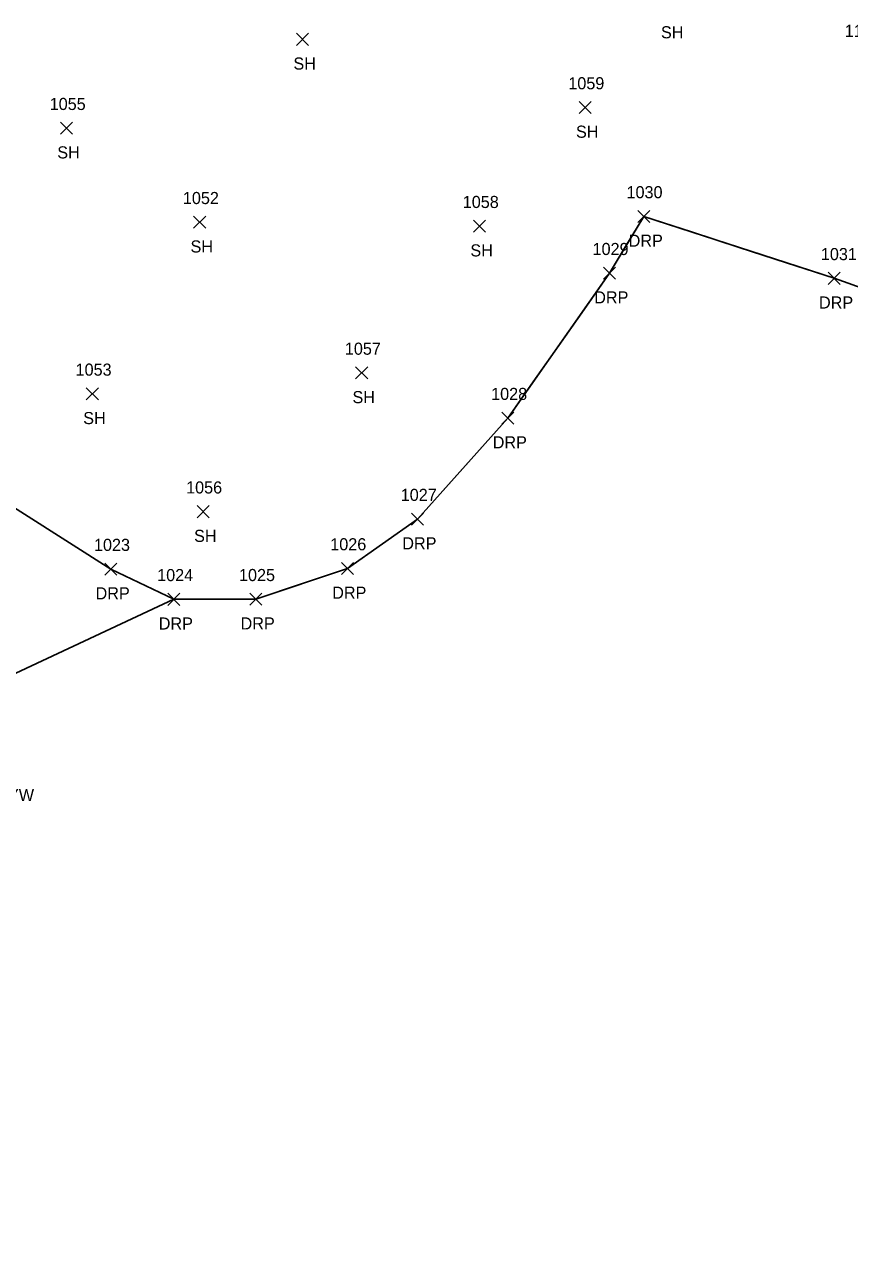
# Model space of a CAD drawing. Extents: x 1639430 to 1640195, y 612006 to 612917.
# Drawn here: x 1639843.9 to 1639980.2, y 612311.8 to 612515.1 of the extents above; entities that cross this region are included whole.
import ezdxf

# ---------------------------------------------------------------- set-up
doc = ezdxf.new("R2010")
doc.units = 0
for name, color, linetype in [('L_A', 7, 'Continuous'), ('L_I', 7, 'Continuous'), ('L_TIC', 7, 'Continuous'), ('LSOGP', 7, 'Continuous'), ('R_A', 7, 'Continuous'), ('R_I', 7, 'Continuous'), ('R_TIC', 7, 'Continuous'), ('RDP', 7, 'Continuous'), ('U_A', 7, 'Continuous')]:
    doc.layers.add(name, color=color, linetype=linetype)

msp = doc.modelspace()

# ---------------------------------------------------------------- linework, layer by layer
at = {"layer": 'L_TIC'}
for points in [[(1639888.84, 612511.69), (1639890.84, 612513.69)], [(1639890.84, 612511.69), (1639888.84, 612513.69)], [(1639935.53, 612500.43), (1639937.53, 612502.43)], [(1639937.53, 612500.43), (1639935.53, 612502.43)], [(1639849.83, 612497.01), (1639851.83, 612499.01)], [(1639851.83, 612497.01), (1639849.83, 612499.01)], [(1639871.84, 612481.47), (1639873.84, 612483.47)], [(1639873.84, 612481.47), (1639871.84, 612483.47)], [(1639918.08, 612480.82), (1639920.08, 612482.82)], [(1639920.08, 612480.82), (1639918.08, 612482.82)], [(1639898.6, 612456.58), (1639900.6, 612458.58)], [(1639900.6, 612456.58), (1639898.6, 612458.58)], [(1639854.11, 612453.12), (1639856.11, 612455.12)], [(1639856.11, 612453.12), (1639854.11, 612455.12)], [(1639872.43, 612433.66), (1639874.43, 612435.66)], [(1639874.43, 612433.66), (1639872.43, 612435.66)]]:
    msp.add_lwpolyline(points, dxfattribs=at)
at = {"layer": 'LSOGP'}
for points in [[(1639868.59, 612420.18), (1639875.35, 612420.18), (1639882.11, 612420.19), (1639889.68, 612422.73), (1639897.25, 612425.27), (1639903.04, 612429.35), (1639908.83, 612433.43), (1639912.57, 612437.6), (1639916.3, 612441.77), (1639920.04, 612445.94), (1639923.77, 612450.11), (1639927.96, 612456.1), (1639932.16, 612462.08), (1639936.35, 612468.07), (1639940.54, 612474.05), (1639943.39, 612478.74), (1639946.23, 612483.43), (1639954.09, 612480.88), (1639961.96, 612478.32), (1639969.82, 612475.76), (1639977.68, 612473.21), (1639983.69, 612471.07)], [(1639728.6, 612301.29), (1639735.53, 612313.13), (1639769.45, 612328.45), (1639770.43, 612331.76), (1639770.95, 612334.08), (1639773.74, 612342.38), (1639775.25, 612344.87), (1639777.85, 612348.84), (1639826.23, 612376.84), (1639832.09, 612385.7), (1639840.76, 612391.84), (1639840.72, 612407.15), (1639868.59, 612420.18)]]:
    msp.add_lwpolyline(points, dxfattribs=at)
at = {"layer": 'R_TIC'}
for points in [[(1639945.23, 612482.43), (1639947.23, 612484.43)], [(1639947.23, 612482.43), (1639945.23, 612484.43)], [(1639939.54, 612473.05), (1639941.54, 612475.05)], [(1639941.54, 612473.05), (1639939.54, 612475.05)], [(1639976.68, 612472.21), (1639978.68, 612474.21)], [(1639978.68, 612472.21), (1639976.68, 612474.21)], [(1639922.77, 612449.11), (1639924.77, 612451.11)], [(1639924.77, 612449.11), (1639922.77, 612451.11)], [(1639907.83, 612432.43), (1639909.83, 612434.43)], [(1639909.83, 612432.43), (1639907.83, 612434.43)], [(1639857.15, 612424.17), (1639859.15, 612426.17)], [(1639859.15, 612424.17), (1639857.15, 612426.17)], [(1639896.25, 612424.27), (1639898.25, 612426.27)], [(1639898.25, 612424.27), (1639896.25, 612426.27)], [(1639867.59, 612419.18), (1639869.59, 612421.18)], [(1639869.59, 612419.18), (1639867.59, 612421.18)], [(1639881.11, 612419.19), (1639883.11, 612421.19)], [(1639883.11, 612419.19), (1639881.11, 612421.19)]]:
    msp.add_lwpolyline(points, dxfattribs=at)
at = {"layer": 'RDP'}
msp.add_lwpolyline([(1639791.07, 612492.27), (1639790.56, 612482.42), (1639792.35, 612472.77), (1639797.16, 612465.25), (1639817.68, 612451.17), (1639836.4, 612438.97), (1639858.15, 612425.17), (1639868.59, 612420.18), (1639882.11, 612420.19), (1639897.25, 612425.27), (1639908.83, 612433.43), (1639923.77, 612450.11), (1639940.54, 612474.05), (1639946.23, 612483.43), (1639977.68, 612473.21), (1640001.7, 612464.66), (1640045.39, 612450.23), (1640094.56, 612433.69), (1640113.57, 612427.07)], dxfattribs=at)

# ---------------------------------------------------------------- texts
at = {"layer": 'L_A'}
for p in [(1639949.06, 612512.85), (1639888.33, 612507.69), (1639935.02, 612496.43), (1639849.32, 612493.01), (1639871.33, 612477.47), (1639917.57, 612476.82), (1639898.09, 612452.58), (1639853.6, 612449.12), (1639871.92, 612429.66)]:
    msp.add_text('SH', height=2, dxfattribs=at).set_placement(p)
at = {"layer": 'L_I'}
for s, p in [('1169', (1639979.42, 612513.09)), ('1059', (1639933.75, 612504.43)), ('1055', (1639848.06, 612501.01)), ('1052', (1639870.07, 612485.47)), ('1058', (1639916.31, 612484.82)), ('1057', (1639896.83, 612460.58)), ('1053', (1639852.34, 612457.12)), ('1056', (1639870.6, 612437.66))]:
    msp.add_text(s, height=2, dxfattribs=at).set_placement(p)
at = {"layer": 'R_A'}
for p in [(1639943.72, 612478.43), (1639938.03, 612469.05), (1639975.17, 612468.21), (1639921.26, 612445.11), (1639906.32, 612428.43), (1639855.64, 612420.17), (1639894.74, 612420.27), (1639866.08, 612415.18), (1639879.6, 612415.19)]:
    msp.add_text('DRP', height=2, dxfattribs=at).set_placement(p)
at = {"layer": 'R_I'}
for s, p in [('1030', (1639943.37, 612486.43)), ('1029', (1639937.76, 612477.05)), ('1031', (1639975.48, 612476.21)), ('1028', (1639921, 612453.11)), ('1027', (1639906.06, 612436.43)), ('1023', (1639855.38, 612428.17)), ('1026', (1639894.42, 612428.27)), ('1024', (1639865.82, 612423.18)), ('1025', (1639879.34, 612423.19))]:
    msp.add_text(s, height=2, dxfattribs=at).set_placement(p)
at = {"layer": 'U_A'}
msp.add_text('GUYW', height=2, dxfattribs=at).set_placement((1639837.16, 612386.84))

doc.saveas('drawing.dxf')
